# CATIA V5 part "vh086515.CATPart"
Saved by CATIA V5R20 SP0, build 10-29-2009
Part number: VA_08-antigiro3D-web
Revision: ANY
Definition: UNKNOWN
Nomenclature: VA_08-antigiro3D-web
Source: Unknown
Bounding box of the stored display mesh (mm): x -4 to 3.804, y -2.9 to 12.1, z -4 to 4
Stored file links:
  C:\Users\Utente\Desktop\IO LAVORO\3D X SITO CF\CUMSA\3D files VH\vh086515.CATPart
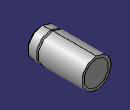
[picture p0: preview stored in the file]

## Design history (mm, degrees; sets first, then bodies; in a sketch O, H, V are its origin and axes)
Body1 "VA-08_variante_antigiro3D-web-1-solid1" (main body)
  Solid1: solid without history
Body2 "TAPA3D-web-1-solid1"
  Solid2: solid without history
Body3 "VA08_Tuerca_giro_v23D-web-1-solid1"
  Solid3: solid without history
Body4 "Obturador_aire3D-web-1-solid1"
  Solid4: solid without history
